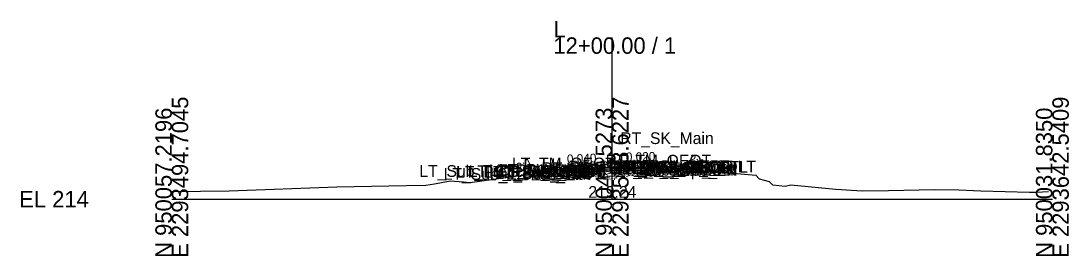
# Model space of a CAD drawing. Extents: x -26 to 7053, y -10 to 7035.
# Drawn here: x -25.7 to 152.8, y -9.7 to 30.4 of the extents above; entities that cross this region are included whole.
import ezdxf

# ---------------------------------------------------------------- set-up
doc = ezdxf.new("R2010")
doc.units = 0
for name, color, linetype in [('Default', 7, 'Continuous'), ('Exist Cross Section Cell', 7, 'Continuous'), ('Exist XS Center Line Elevation Label', 7, 'Continuous'), ('Exist XS Ground Line', 7, 'Continuous'), ('Prop CMT Pvmt Course 1', 7, 'Continuous'), ('Prop CMT Pvmt Course 2', 7, 'Continuous'), ('Prop CMT Pvmt Surface', 7, 'Continuous'), ('Prop CMT Pvmt Surface Overlay', 7, 'Continuous'), ('Prop CMT Pvmt Surface Shoulder', 7, 'Continuous'), ('Prop CMT Shld Paved Course 1', 7, 'Continuous'), ('Prop CMT Shld Paved Course 2', 7, 'Continuous'), ('Prop CMT Slope Grass', 7, 'Continuous'), ('Prop CMT Subgrade Earthwork', 7, 'Continuous'), ('Prop XS EOT Tick Mark', 7, 'Continuous'), ('Prop XS SE Text', 7, 'Continuous'), ('Prop XS Side Slope Text', 7, 'Continuous')]:
    doc.layers.add(name, color=color, linetype=linetype)

msp = doc.modelspace()

# ---------------------------------------------------------------- linework, layer by layer
at = {"layer": 'Exist Cross Section Cell'}
for p, q in [((75, 0), (75, 27.58)), ((0, 0), (75, 0)), ((75, 0), (150, 0))]:
    msp.add_line(p, q, dxfattribs=at)
at = {"layer": 'Exist XS Ground Line'}
for p, q in [((50.75, 2.85), (61.38, 4.31)), ((61.38, 4.31), (64.41, 4.71)), ((64.41, 4.71), (64.96, 4.79)), ((64.96, 4.79), (65.84, 4.83)), ((65.84, 4.83), (71.39, 5.05)), ((71.39, 5.05), (74.93, 5.24)), ((74.93, 5.24), (78.31, 5.26)), ((78.31, 5.26), (84.55, 5.33)), ((84.55, 5.33), (92.33, 4.74)), ((92.33, 4.74), (99.47, 4.1)), ((99.47, 4.1), (100.03, 3.47)), ((9.79, 1.44), (28.11, 2.09)), ((28.11, 2.09), (39.91, 2.31)), ((39.91, 2.31), (43.28, 2.39)), ((43.28, 2.39), (44.75, 2.63)), ((44.75, 2.63), (47.4, 3.11)), ((47.4, 3.11), (49.67, 2.98)), ((49.67, 2.98), (50.75, 2.85)), ((100.03, 3.47), (101.75, 3.04)), ((101.75, 3.04), (102.33, 2.44)), ((102.33, 2.44), (104.46, 2.22)), ((104.46, 2.22), (105.44, 2.47)), ((105.44, 2.47), (113.12, 1.73)), ((0, 1.33), (9.79, 1.44)), ((113.12, 1.73), (117.61, 1.44)), ((117.61, 1.44), (122.09, 1.5)), ((122.09, 1.5), (129.92, 1.67)), ((129.92, 1.67), (134.05, 1.59)), ((134.05, 1.59), (137.82, 1.45)), ((137.82, 1.45), (146.12, 1.2)), ((146.12, 1.2), (147.32, 1.22)), ((147.32, 1.22), (149.32, 1.3))]:
    msp.add_line(p, q, dxfattribs=at)
at = {"layer": 'Prop CMT Pvmt Course 1'}
for points in [[(75, 5.4), (65, 5)], [(75, 5.4), (85, 5.6)], [(75, 5.27), (75, 5.4)], [(75, 5.27), (75, 5.4)], [(85, 5.6), (85, 5.35)], [(65, 4.75), (75, 5.15)], [(65, 5), (65, 4.75)], [(85, 5.35), (75, 5.15)], [(75, 5.15), (75, 5.27), (75, 5.27)], [(75, 5.15), (75, 5.27), (75, 5.27)]]:
    msp.add_lwpolyline(points, dxfattribs=at)
at = {"layer": 'Prop CMT Pvmt Course 2'}
for points in [[(75, 5.15), (65, 4.75)], [(65, 4.42), (75, 4.82)], [(65, 4.75), (65, 4.42)], [(75, 5.15), (85, 5.35)], [(75, 4.82), (75, 5.15)], [(75, 4.82), (75, 5.15)], [(85, 5.02), (75, 4.82)], [(85, 5.35), (85, 5.02)]]:
    msp.add_lwpolyline(points, dxfattribs=at)
at = {"layer": 'Prop CMT Pvmt Surface'}
for points in [[(75, 5.4), (65, 5)], [(75, 5.4), (85, 5.6)]]:
    msp.add_lwpolyline(points, dxfattribs=at)
at = {"layer": 'Prop CMT Pvmt Surface Overlay'}
for points in [[(75, 5.4), (65, 5)], [(75, 5.4), (85, 5.6)]]:
    msp.add_lwpolyline(points, dxfattribs=at)
at = {"layer": 'Prop CMT Pvmt Surface Shoulder'}
for points in [[(85, 5.6), (85.46, 5.61)], [(65, 5), (63.22, 4.93)]]:
    msp.add_lwpolyline(points, dxfattribs=at)
at = {"layer": 'Prop CMT Shld Paved Course 1'}
for points in [[(85, 5.6), (85.46, 5.61), (85.7, 5.36)], [(85, 5.35), (85, 5.6)], [(85.7, 5.36), (85, 5.35)], [(65, 5), (63.22, 4.93), (62.96, 4.67)], [(62.96, 4.67), (65, 4.75)], [(65, 4.75), (65, 5)]]:
    msp.add_lwpolyline(points, dxfattribs=at)
at = {"layer": 'Prop CMT Shld Paved Course 2'}
for points in [[(85, 5.35), (85.7, 5.36), (86.2, 5.37), (86.53, 5.05)], [(65, 4.75), (62.96, 4.67), (62.46, 4.65), (62.11, 4.3)], [(62.11, 4.3), (65, 4.42)], [(65, 4.42), (65, 4.75)], [(85, 5.02), (85, 5.35)], [(86.53, 5.05), (85, 5.02)]]:
    msp.add_lwpolyline(points, dxfattribs=at)
at = {"layer": 'Prop CMT Slope Grass'}
for points in [[(85.46, 5.61), (88, 5.51)], [(88, 5.51), (89.04, 4.99)], [(61.2, 4.77), (59.89, 4.11)], [(63.22, 4.93), (61.2, 4.77)]]:
    msp.add_lwpolyline(points, dxfattribs=at)
at = {"layer": 'Prop CMT Subgrade Earthwork'}
for points in [[(86.53, 5.05), (87.03, 5.55)], [(62.11, 4.3), (61.61, 4.8)], [(65, 4.42), (62.11, 4.3)], [(75, 4.82), (65, 4.42)], [(75, 4.82), (85, 5.02)], [(85, 5.02), (86.53, 5.05)]]:
    msp.add_lwpolyline(points, dxfattribs=at)
at = {"layer": 'Prop XS EOT Tick Mark'}
for p, q in [((85, 5.6), (85, 7.51)), ((65, 5), (65, 6.91))]:
    msp.add_line(p, q, dxfattribs=at)

# ---------------------------------------------------------------- texts
at = {"layer": 'Default'}
for s, height, p in [('RT_SK_Main', 2, (76.4, 9.4)), ('RT_TM_OEOT', 2, (73.9, 5.56)), ('LT_Sub_Trench_Out_DLT', 2, (42.18, 3.8)), ('LT_Sub_Trench_Out', 2, (46.32, 3.3)), ('LT_PS2_Shelf_Out', 2, (48.44, 3.65)), ('LT_GS_OS_CTL', 2, (50.57, 3.77)), ('LT_PS2_OEOP', 2, (53.2, 3.67)), ('LT_PS1_OEOP', 2, (54.02, 3.93)), ('LT_Sub_OEOT', 2, (55.08, 3.42)), ('LT_PV2_OEOT', 2, (55.17, 3.75)), ('LT_PV1_OEOT', 2, (55.74, 4)), ('LT_TM_OEOT', 2, (57.94, 5.08)), ('RT_PV1_OEEOP_W', 2, (62.94, 4.27)), ('LT_PV1_OEEOP_W', 2, (62.98, 4.27)), ('RT_Sub_OEEOP', 2, (64.17, 3.82)), ('LT_Sub_OEEOP', 2, (64.21, 3.82)), ('RT_PV2_OEEOP', 2, (64.26, 4.15)), ('LT_PV2_OEEOP', 2, (64.31, 4.15)), ('RT_Sub_Trench_Out_DLT', 2, (67.55, 4.55)), ('PV1_PGL_W', 2, (67.58, 4.27)), ('PV1_PGL', 2, (69.47, 4.4)), ('RT_Sub_Trench_Out', 2, (70.69, 4.05)), ('RT_PS2_Shelf_Out', 2, (72.14, 4.37)), ('RT_Sub_OEOT', 2, (75.03, 4.02)), ('RT_PV2_OEOT', 2, (75.13, 4.35)), ('RT_PV1_OEOT', 2, (75.69, 4.6)), ('RT_PS2_OEOP', 2, (75.89, 4.36)), ('RT_PS1_OEOP', 2, (76.21, 4.61)), ('RT_GS_OS_CTL', 2, (77.32, 4.51)), ('RT_Slope_Fill', 2, (79.52, 3.99)), ('LT_Slope_Fill', 2, (50.41, 3.11)), ('LT_Slope_Fill', 2, (50.41, 3.11)), ('-', 0.0001, (0, 0))]:
    msp.add_text(s, height=height, dxfattribs=at).set_placement(p)
at = {"layer": 'Exist Cross Section Cell'}
for s, p in [('L', (65, 27.58)), ('12+00.00 / 1', (65, 24.78)), ('EL 214', (-26, -1.4))]:
    msp.add_text(s, height=2.8, dxfattribs=at).set_placement(p)
for s, p in [('E 2293494.7045', (2.8, -10)), ('E 2293568.6227', (77.8, -10)), ('E 2293642.5409', (152.8, -10)), ('N 950057.2196', (0, -10)), ('N 950044.5273', (75, -10)), ('N 950031.8350', (150, -10))]:
    msp.add_text(s, height=2.8, rotation=90, dxfattribs=at).set_placement(p)
at = {"layer": 'Exist XS Center Line Elevation Label'}
msp.add_text('219.24', height=2, dxfattribs=at).set_placement((70.96, 0.24))
at = {"layer": 'Prop XS SE Text'}
for s, rotation, p in [('0.040', 2.2906, (67.34, 6.09)), ('0.020', 1.1458, (77.36, 6.45))]:
    msp.add_text(s, height=1.5, rotation=rotation, dxfattribs=at).set_placement(p)
at = {"layer": 'Prop XS Side Slope Text'}
for rotation, p in [(333.4349, (87.79, 6.45)), (26.565, (59.15, 4.58))]:
    msp.add_text('2:1', height=1.5, rotation=rotation, dxfattribs=at).set_placement(p)

doc.saveas('drawing.dxf')
